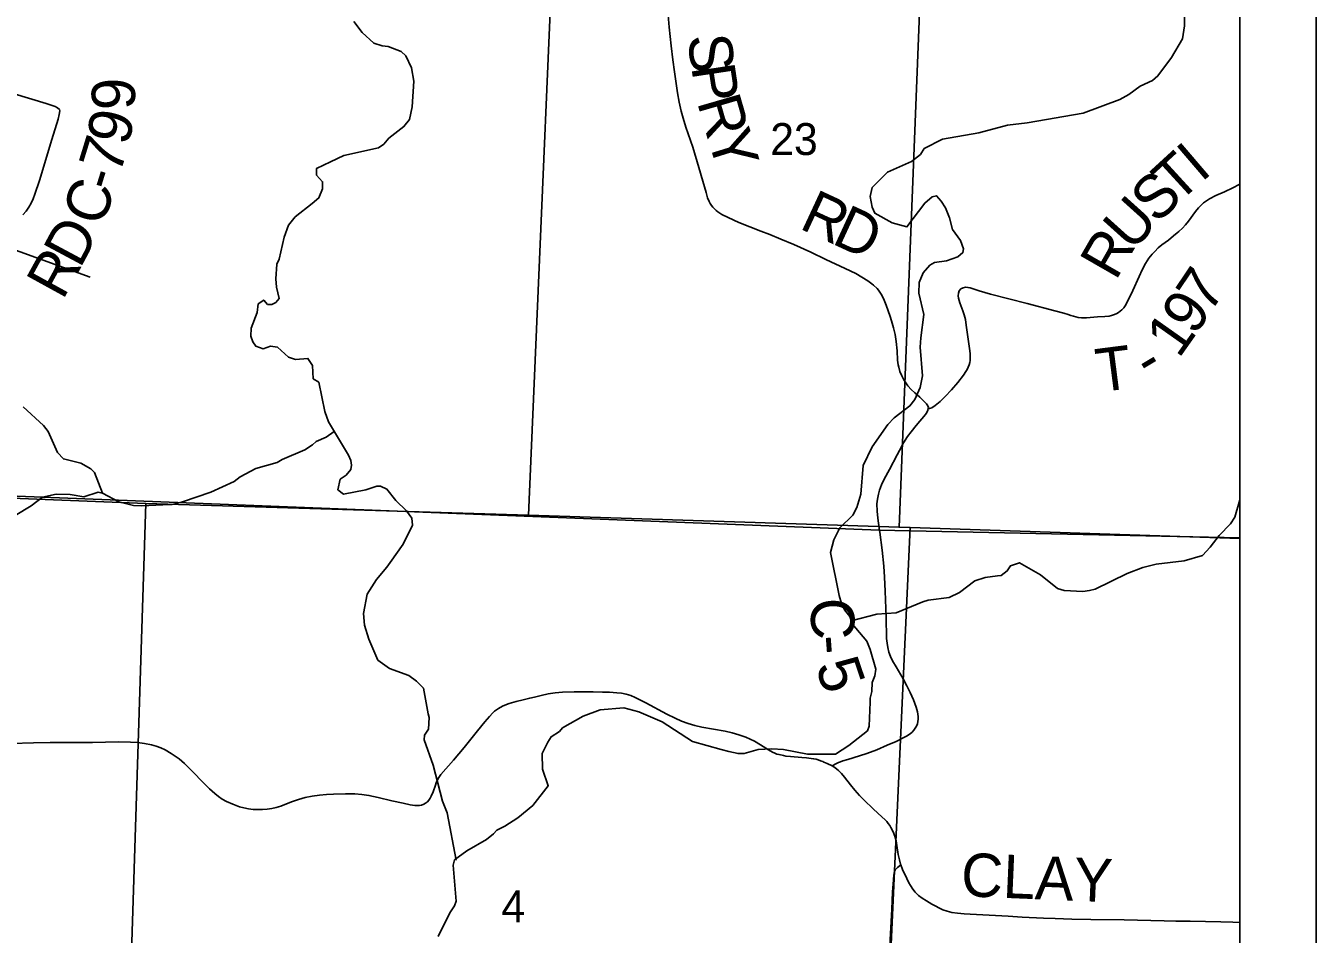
# Model space of a CAD drawing. Extents: x 0 to 34, y 0 to 22.
# Drawn here: x 7.308 to 9, y 14.614 to 15.804 of the extents above; entities that cross this region are included whole.
import ezdxf

# ---------------------------------------------------------------- set-up
doc = ezdxf.new("R2010")
doc.units = 0
for name, color, linetype in [('GM_X_County_Road', 7, 'Continuous'), ('GM_X_County_Road_Text', 7, 'Continuous'), ('GM_X_Minor_River', 7, 'Continuous'), ('GM_X_Rail_Line', 7, 'Continuous'), ('GM_X_Section', 7, 'Continuous'), ('GM_X_Section_Text', 7, 'Continuous'), ('GM_X_Township_Road', 7, 'Continuous'), ('GM_X_Township_Road_Text', 7, 'Continuous'), ('GM_X_Unincorporated_Text', 7, 'Continuous'), ('SH_Data', 7, 'Continuous')]:
    doc.layers.add(name, color=color, linetype=linetype)

msp = doc.modelspace()

# ---------------------------------------------------------------- linework, layer by layer
at = {"layer": 'GM_X_County_Road'}
msp.add_line((7.2752, 15.5169), (7.3927, 15.4747), dxfattribs=at)
for points in [[(8.4914, 15.3023), (8.4917, 15.3036), (8.491, 15.3058), (8.4889, 15.3085), (8.4859, 15.3116), (8.4804, 15.3172), (8.4737, 15.3231), (8.469, 15.3274), (8.4647, 15.3323), (8.461, 15.3372), (8.4594, 15.3398), (8.4566, 15.3451), (8.4543, 15.3508), (8.4527, 15.3567), (8.4521, 15.3596), (8.4512, 15.3656), (8.4504, 15.3778), (8.4495, 15.3901), (8.4481, 15.3993), (8.4459, 15.4083), (8.4433, 15.4172), (8.4413, 15.4231), (8.4362, 15.4378), (8.4327, 15.4465), (8.4298, 15.4521), (8.4263, 15.4573), (8.4242, 15.4597), (8.4197, 15.4641), (8.4173, 15.466), (8.4122, 15.4697), (8.4043, 15.4747), (8.3962, 15.4792), (8.3824, 15.4859), (8.3572, 15.4979), (8.3376, 15.5071), (8.315, 15.5173), (8.2979, 15.5245), (8.2835, 15.5304), (8.2719, 15.5349), (8.2575, 15.5404), (8.2431, 15.5462), (8.229, 15.5526), (8.2208, 15.5568), (8.2156, 15.56), (8.2132, 15.5619), (8.211, 15.5639), (8.2089, 15.5661), (8.2071, 15.5685), (8.2055, 15.571), (8.204, 15.5737), (8.2021, 15.5783), (8.2, 15.5855), (8.1958, 15.6002), (8.1907, 15.6181), (8.1825, 15.6449), (8.1736, 15.6713), (8.1699, 15.683), (8.1675, 15.6919), (8.1649, 15.704), (8.1628, 15.7162), (8.1585, 15.7438), (8.1563, 15.7592), (8.1541, 15.7776), (8.1516, 15.8023), (8.1505, 15.8177)], [(7.2128, 15.7391), (7.2661, 15.7227), (7.293, 15.7146), (7.3349, 15.7022), (7.3438, 15.6992), (7.3467, 15.698), (7.3496, 15.6965), (7.3525, 15.6944)], [(7.3041, 15.5564), (7.3084, 15.561), (7.3121, 15.5661), (7.3153, 15.5716), (7.3179, 15.5774), (7.3201, 15.5832), (7.3259, 15.6011), (7.3422, 15.6548), (7.3504, 15.6817), (7.3519, 15.6878), (7.3526, 15.6925), (7.3525, 15.6944)], [(8.4277, 15.1404), (8.4275, 15.1424), (8.4252, 15.1585), (8.4242, 15.1677), (8.424, 15.1775), (8.4248, 15.1838), (8.426, 15.1901), (8.4275, 15.1954), (8.4299, 15.2022), (8.4334, 15.2097), (8.4405, 15.2224), (8.4507, 15.2417), (8.4536, 15.2472), (8.4591, 15.2573), (8.4642, 15.2659), (8.4689, 15.272), (8.4754, 15.2802), (8.4878, 15.2946), (8.4896, 15.2974), (8.491, 15.3003), (8.4914, 15.3023)], [(8.3655, 14.834), (8.3709, 14.8372), (8.3737, 14.8386), (8.3764, 14.8395), (8.3793, 14.8407), (8.3859, 14.8425), (8.3931, 14.8445), (8.4109, 14.8502), (8.424, 14.8553), (8.4377, 14.8612), (8.4493, 14.8661), (8.4628, 14.8728), (8.4677, 14.8761), (8.4703, 14.8784), (8.4723, 14.8809), (8.4743, 14.8834), (8.4759, 14.8862), (8.4771, 14.8892), (8.4779, 14.8924), (8.4782, 14.8955), (8.4782, 14.8987), (8.4778, 14.9019), (8.4772, 14.905), (8.4756, 14.9111), (8.472, 14.9208), (8.4677, 14.9302), (8.4634, 14.939), (8.4583, 14.9482), (8.4491, 14.9638), (8.4444, 14.9718), (8.4418, 14.9773), (8.4397, 14.9831), (8.4383, 14.989), (8.4373, 14.9951), (8.4367, 15.0012), (8.4362, 15.0291), (8.4349, 15.0632), (8.434, 15.0816), (8.4332, 15.0958), (8.4309, 15.1168), (8.4277, 15.1404)], [(7.2593, 14.8625), (7.3183, 14.8641), (7.34, 14.8645), (7.374, 14.8646), (7.3957, 14.8649), (7.4298, 14.8656), (7.4453, 14.8653), (7.4547, 14.8646), (7.4639, 14.8633), (7.4731, 14.8615), (7.4792, 14.8598), (7.4851, 14.8576), (7.4908, 14.855), (7.4989, 14.8503), (7.5041, 14.8469), (7.5091, 14.8432), (7.5162, 14.837), (7.5273, 14.8261), (7.5402, 14.8127), (7.5491, 14.804), (7.556, 14.7979), (7.5608, 14.794), (7.5658, 14.7906), (7.5711, 14.7876), (7.5795, 14.7838), (7.5882, 14.7806), (7.594, 14.779), (7.6, 14.7778), (7.6061, 14.7771), (7.6122, 14.7767), (7.6183, 14.7768), (7.6244, 14.7772), (7.6305, 14.7781), (7.6364, 14.7795), (7.6423, 14.7814), (7.6566, 14.7871), (7.6655, 14.7902), (7.6746, 14.7926), (7.6838, 14.7943), (7.6931, 14.7955), (7.7024, 14.7964), (7.7117, 14.7968), (7.7272, 14.7973), (7.7395, 14.7973), (7.7488, 14.7967), (7.758, 14.7953), (7.7701, 14.7927), (7.788, 14.7883), (7.8031, 14.785), (7.8121, 14.7831), (7.8182, 14.7822), (7.8212, 14.782), (7.8242, 14.7822), (7.8271, 14.7828), (7.8298, 14.7838), (7.8324, 14.7852), (7.8346, 14.7871), (7.8366, 14.7893), (7.8383, 14.7917), (7.8397, 14.7944), (7.8421, 14.8), (7.8451, 14.8089), (7.8462, 14.8118), (7.849, 14.8175), (7.8525, 14.8227), (7.8687, 14.8416), (7.8829, 14.858), (7.9003, 14.8798), (7.91, 14.8919), (7.9161, 14.899), (7.9203, 14.9036), (7.9226, 14.9057), (7.9251, 14.9076), (7.9277, 14.9094), (7.9332, 14.9125), (7.9361, 14.9138), (7.942, 14.9159), (7.9511, 14.9183), (7.9601, 14.9205), (7.9689, 14.9229), (7.9749, 14.9242), (7.9839, 14.9265), (7.993, 14.9284), (8.0022, 14.9298), (8.0116, 14.9306), (8.0271, 14.9311), (8.052, 14.931), (8.0643, 14.9308), (8.0736, 14.9306), (8.083, 14.93), (8.0892, 14.9292), (8.0953, 14.9279), (8.1014, 14.9262), (8.1072, 14.9238), (8.1211, 14.9168), (8.1484, 14.902), (8.1595, 14.8965), (8.1679, 14.8927), (8.1766, 14.8895), (8.1855, 14.8869), (8.1945, 14.885), (8.2098, 14.8822), (8.2251, 14.8794), (8.2342, 14.8773), (8.2432, 14.8747), (8.252, 14.8715), (8.2578, 14.8691), (8.2634, 14.8663), (8.2714, 14.8615), (8.2819, 14.8549), (8.2873, 14.8519), (8.29, 14.8507), (8.2929, 14.8496), (8.2958, 14.8488), (8.3017, 14.8475), (8.3047, 14.847), (8.3107, 14.8463), (8.3258, 14.8452), (8.3319, 14.8447), (8.338, 14.8439), (8.3411, 14.8434), (8.3442, 14.8427), (8.3472, 14.8419), (8.3502, 14.8409), (8.353, 14.8398), (8.3546, 14.8391), (8.3587, 14.8374), (8.3655, 14.834)], [(8.3655, 14.834), (8.3687, 14.8321), (8.3715, 14.8299), (8.3738, 14.8278), (8.3774, 14.8241), (8.3814, 14.8191), (8.3892, 14.8094), (8.395, 14.8022), (8.4011, 14.7952), (8.4076, 14.7886), (8.4189, 14.7781), (8.4258, 14.7718), (8.4349, 14.7632), (8.437, 14.761), (8.439, 14.7586), (8.4409, 14.756), (8.4425, 14.7533), (8.4452, 14.7476), (8.4475, 14.7418), (8.4492, 14.7358), (8.4502, 14.7296), (8.452, 14.7181), (8.4535, 14.7109), (8.455, 14.7054), (8.4554, 14.7042)], [(8.4554, 14.7042), (8.4577, 14.6981), (8.4631, 14.6865), (8.4658, 14.681), (8.4679, 14.6771), (8.471, 14.6723), (8.4742, 14.6686), (8.4786, 14.6644), (8.4835, 14.6606), (8.4892, 14.6572), (8.4962, 14.6529), (8.5103, 14.6456), (8.5162, 14.6436), (8.5222, 14.6421), (8.5296, 14.6411), (8.5384, 14.6401), (8.5465, 14.6396), (8.596, 14.637), (8.6146, 14.636), (8.6425, 14.6347), (8.6579, 14.634), (8.6797, 14.6334), (8.7045, 14.6327), (8.7483, 14.6321), (8.8006, 14.631), (8.8161, 14.6307), (8.8347, 14.6304), (8.8751, 14.6298), (8.8906, 14.6293), (8.9, 14.6289)]]:
    msp.add_lwpolyline(points, dxfattribs=at)
at = {"layer": 'GM_X_Minor_River'}
for points in [[(7.7382, 15.8095), (7.7492, 15.7951), (7.7645, 15.7812), (7.7755, 15.7775), (7.7831, 15.7768), (7.8002, 15.7704), (7.8063, 15.7648), (7.8139, 15.7489), (7.8171, 15.7314), (7.8147, 15.6976), (7.8114, 15.6813), (7.8039, 15.6718), (7.7843, 15.6568), (7.7775, 15.6488), (7.7707, 15.6442), (7.725, 15.6341), (7.7076, 15.6256)], [(8.8274, 15.8178), (8.8275, 15.8038), (8.8246, 15.7871), (8.8104, 15.7623), (8.7924, 15.7383), (8.7852, 15.7322), (8.769, 15.7249), (8.7543, 15.7138), (8.7426, 15.7073), (8.6946, 15.6895), (8.6212, 15.6769), (8.5951, 15.6737), (8.5577, 15.6636), (8.51, 15.6553), (8.4862, 15.643), (8.481, 15.6354), (8.4693, 15.6262), (8.4379, 15.612), (8.418, 15.5921), (8.4151, 15.5803), (8.4178, 15.5663), (8.4213, 15.5584), (8.4441, 15.5456), (8.4634, 15.5404), (8.4867, 15.5717), (8.4965, 15.5797), (8.5022, 15.5813), (8.5083, 15.5741), (8.514, 15.5654), (8.5194, 15.5525), (8.5233, 15.537), (8.5336, 15.5226), (8.5375, 15.5117), (8.5368, 15.5067), (8.53, 15.501), (8.5152, 15.496), (8.4994, 15.4936), (8.4933, 15.4901), (8.4847, 15.4802), (8.4795, 15.4677), (8.4792, 15.4536), (8.4854, 15.4256), (8.4815, 15.3952), (8.4808, 15.383), (8.4837, 15.3451), (8.4808, 15.3299), (8.4737, 15.3143), (8.4673, 15.3059), (8.4466, 15.2902), (8.4383, 15.2814), (8.4177, 15.2521), (8.4061, 15.2277), (8.403, 15.1901), (8.3978, 15.1726), (8.3925, 15.1627), (8.3756, 15.1459), (8.3674, 15.1303), (8.3633, 15.1136), (8.3747, 15.0575), (8.3774, 15.0469), (8.3816, 15.0386), (8.3885, 15.0299), (8.3916, 15.0204)], [(7.6838, 15.5713), (7.6924, 15.5785), (7.6972, 15.5903), (7.6972, 15.5997), (7.6891, 15.6084), (7.6891, 15.6168), (7.7076, 15.6256)], [(7.6838, 15.5713), (7.6615, 15.5537), (7.6525, 15.5426), (7.6469, 15.527), (7.6403, 15.4981), (7.6373, 15.4916), (7.6359, 15.4723), (7.6367, 15.4613), (7.6402, 15.4468), (7.636, 15.4415), (7.6307, 15.4388), (7.6251, 15.4388), (7.6201, 15.4445), (7.6126, 15.4395), (7.6115, 15.4281), (7.6037, 15.4079), (7.6033, 15.3973), (7.606, 15.3897), (7.6098, 15.384), (7.6193, 15.3806), (7.6291, 15.3841), (7.6382, 15.3826), (7.6527, 15.3698), (7.6617, 15.3668), (7.678, 15.368), (7.6841, 15.3586), (7.685, 15.3415), (7.6925, 15.337)], [(7.6925, 15.337), (7.7, 15.2984), (7.705, 15.2848), (7.7314, 15.2413), (7.7345, 15.2345), (7.7353, 15.228), (7.7342, 15.2227), (7.7282, 15.2151), (7.7203, 15.2097), (7.7174, 15.196), (7.7246, 15.19), (7.7541, 15.1959), (7.7685, 15.2005), (7.7734, 15.2006), (7.7817, 15.1965), (7.7932, 15.1817), (7.8073, 15.1685), (7.8142, 15.1587), (7.815, 15.1496), (7.8027, 15.1245), (7.7858, 15.1008), (7.7813, 15.0947), (7.7678, 15.0783), (7.7558, 15.0593), (7.751, 15.0338), (7.7523, 15.0186), (7.7581, 15.0001), (7.7696, 14.9728), (7.7852, 14.9615), (7.8103, 14.9526), (7.8206, 14.9451), (7.8294, 14.936), (7.8356, 14.9023), (7.8368, 14.8973), (7.8362, 14.8822), (7.8309, 14.8742), (7.8306, 14.8681), (7.8422, 14.8348), (7.8546, 14.7878), (7.8604, 14.7726), (7.8726, 14.7105)], [(7.6839, 15.2549), (7.6741, 15.2484), (7.6443, 15.2357), (7.6379, 15.2315), (7.6099, 15.2237), (7.5892, 15.213), (7.5812, 15.2069), (7.5507, 15.1927), (7.5137, 15.1799), (7.5001, 15.1768), (7.4876, 15.1764), (7.4604, 15.1747), (7.4494, 15.1754), (7.4301, 15.1802), (7.4088, 15.1915), (7.3981, 15.2184), (7.3935, 15.2233), (7.3803, 15.2309), (7.3575, 15.2364), (7.3499, 15.2447), (7.3373, 15.2724), (7.3312, 15.28), (7.3046, 15.3045)], [(7.6839, 15.2549), (7.6889, 15.2593), (7.7021, 15.265), (7.7126, 15.2723)], [(7.41, 15.1909), (7.4028, 15.193), (7.3843, 15.1868), (7.3661, 15.1898), (7.3479, 15.19), (7.3302, 15.1862), (7.3151, 15.1747), (7.294, 15.1624)], [(8.3903, 15.0243), (8.4241, 15.0331), (8.4495, 15.0348), (8.4842, 15.0491), (8.4914, 15.0514), (8.5186, 15.0546), (8.5322, 15.0615), (8.5526, 15.0768), (8.5662, 15.0811), (8.5821, 15.0831), (8.587, 15.0835), (8.5949, 15.0896), (8.599, 15.0961), (8.6108, 15.1003), (8.6385, 15.0846), (8.661, 15.0665), (8.6697, 15.0639), (8.694, 15.0625), (8.7027, 15.0637), (8.7102, 15.0657), (8.7521, 15.0864), (8.7725, 15.0942), (8.7903, 15.0984), (8.827, 15.1028), (8.8508, 15.1098), (8.861, 15.1205), (8.8726, 15.1362), (8.8877, 15.1514), (8.8933, 15.1602), (8.9, 15.1826)], [(8.3916, 15.0204), (8.4107, 14.9977), (8.4153, 14.9868), (8.4227, 14.961), (8.4213, 14.9519), (8.4179, 14.9435), (8.4176, 14.9314), (8.4154, 14.9226), (8.4154, 14.9177), (8.4141, 14.8862), (8.4115, 14.8801), (8.3874, 14.8606), (8.3697, 14.8495), (8.3329, 14.8496), (8.3015, 14.8555), (8.2863, 14.8565), (8.2685, 14.8557), (8.25, 14.8502), (8.242, 14.8502), (8.2299, 14.8528), (8.2197, 14.8557), (8.1821, 14.8661), (8.1425, 14.8917), (8.1121, 14.9048), (8.0924, 14.9103), (8.0614, 14.9075), (8.0391, 14.8994), (8.0119, 14.884), (8.0078, 14.8791), (7.9968, 14.8722), (7.9927, 14.8653), (7.9852, 14.8501), (7.9854, 14.8296), (7.9931, 14.808), (7.9728, 14.7821), (7.9532, 14.766), (7.9363, 14.7549), (7.9257, 14.7499), (7.9212, 14.7449), (7.9121, 14.7377), (7.8865, 14.7227), (7.8703, 14.7108), (7.8684, 14.704), (7.8722, 14.6566), (7.8703, 14.6505), (7.8639, 14.6417), (7.849, 14.6105)]]:
    msp.add_lwpolyline(points, dxfattribs=at)
at = {"layer": 'GM_X_Rail_Line'}
msp.add_lwpolyline([(6.4764, 15.22), (8.4272, 15.1429), (8.9, 15.1329), (8.9, 20.2439), (7.9141, 20.2806), (7.3096, 20.3035), (6.6357, 20.3306)], dxfattribs=at)
msp.add_lwpolyline([(6.4223, 14.1), (8.9, 14.1), (8.9, 15.1329), (8.4272, 15.1429), (6.4764, 15.22), (6.4607, 14.8895)], close=True, dxfattribs=at)
at = {"layer": 'GM_X_Section'}
for points in [[(8.0113, 16.1881), (8.4938, 16.1751), (8.4531, 15.1468), (7.9673, 15.1628)], [(7.4655, 15.1779), (7.4338, 14.1789), (6.4272, 14.2142), (6.4755, 15.2172)], [(7.4655, 15.1779), (7.9673, 15.1628), (8.4531, 15.1468), (8.4675, 15.1465), (8.4218, 14.1405), (7.4338, 14.1789)]]:
    msp.add_lwpolyline(points, close=True, dxfattribs=at)
at = {"layer": 'GM_X_Township_Road'}
for points in [[(8.4914, 15.3023), (8.4931, 15.3023), (8.496, 15.3035), (8.5006, 15.3062), (8.5069, 15.3116), (8.5135, 15.318), (8.5217, 15.3269), (8.5301, 15.3365), (8.5376, 15.3459), (8.5408, 15.3508), (8.5426, 15.3537), (8.5439, 15.3565), (8.545, 15.3597), (8.5458, 15.3625), (8.5463, 15.3654), (8.5464, 15.3686), (8.5463, 15.3747), (8.5456, 15.381), (8.5438, 15.3933), (8.5426, 15.4024), (8.5411, 15.4118), (8.54, 15.4189), (8.5384, 15.4253), (8.5367, 15.4305), (8.5327, 15.4411), (8.5318, 15.4441), (8.5311, 15.4472), (8.5308, 15.4503), (8.5311, 15.4535), (8.5321, 15.4566), (8.5341, 15.4591), (8.537, 15.4607), (8.5401, 15.4614), (8.5434, 15.4612), (8.5464, 15.4605), (8.5582, 15.4566), (8.5731, 15.4522), (8.6212, 15.4401), (8.6573, 15.4306), (8.6692, 15.4274), (8.675, 15.4255), (8.6785, 15.4243), (8.6817, 15.4235), (8.6848, 15.4225), (8.6881, 15.4219), (8.6924, 15.4213), (8.6988, 15.4213), (8.7131, 15.4225), (8.723, 15.423), (8.7286, 15.4236), (8.7317, 15.4242), (8.7356, 15.4256), (8.7385, 15.4269), (8.7406, 15.4283), (8.7429, 15.4298), (8.7453, 15.4316), (8.7478, 15.4343), (8.7495, 15.4368), (8.7528, 15.4426), (8.7594, 15.4571), (8.7678, 15.4755), (8.7718, 15.4841), (8.7761, 15.4924), (8.7807, 15.4994), (8.785, 15.5048), (8.7883, 15.5081), (8.7929, 15.5131), (8.7976, 15.5168), (8.8063, 15.5232), (8.8128, 15.5287), (8.8176, 15.5325), (8.82, 15.5344), (8.8245, 15.5386), (8.8286, 15.5431), (8.8324, 15.5479), (8.8416, 15.5604), (8.8456, 15.5652), (8.8499, 15.5697), (8.8522, 15.5718), (8.8547, 15.5738), (8.86, 15.5771), (8.8683, 15.5814), (8.8796, 15.5865), (8.8909, 15.5916), (8.8992, 15.5958), (8.9, 15.5963)], [(8.4407, 14.5901), (8.4434, 14.6462), (8.4447, 14.6688), (8.4453, 14.6792), (8.4464, 14.6908), (8.4471, 14.6957), (8.4481, 14.6978), (8.4496, 14.6998), (8.4509, 14.7009), (8.4526, 14.7021), (8.4554, 14.7042)]]:
    msp.add_lwpolyline(points, dxfattribs=at)
at = {"layer": 'GM_X_Unincorporated_Text'}
for points in [[(8.9, 15.1321), (8.9, 16.1585), (8.4938, 16.1751), (8.4531, 15.1468), (8.4675, 15.1465)], [(8.9, 14.1266), (8.9, 15.1321), (8.4675, 15.1465), (8.4218, 14.1405)]]:
    msp.add_lwpolyline(points, close=True, dxfattribs=at)
at = {"layer": 'SH_Data'}
for p, q in [((9, 21), (9, 14)), ((8.9, 20.9), (8.9, 14.1))]:
    msp.add_line(p, q, dxfattribs=at)

# ---------------------------------------------------------------- texts
at = {"layer": 'GM_X_County_Road_Text'}
for s, height, rotation, p in [('S', 0.0568, 276.6813, (8.1757, 15.7904)), ('P', 0.0568, 278.5845, (8.1805, 15.7503)), ('9', 0.0568, 90.5671, (7.4516, 15.6938)), ('R', 0.0568, 286.155, (8.1879, 15.7044)), ('9', 0.0568, 77.4973, (7.4425, 15.6456)), ('Y', 0.0568, 287.3444, (8.2013, 15.6583)), ('7', 0.0568, 72.8829, (7.431, 15.6073)), ('C', 0.0568, 71.4305, (7.4087, 15.5393)), ('-', 0.0568, 72.7545, (7.424, 15.5849)), ('R', 0.0568, 335.0515, (8.3207, 15.5391)), ('D', 0.0568, 335.211, (8.3632, 15.5193)), ('D', 0.0568, 61.8656, (7.3792, 15.4848)), ('R', 0.0568, 61.2229, (7.3565, 15.4433)), ('C', 0.0568, 271.0734, (8.3371, 15.0538)), ('-', 0.0568, 274.2242, (8.3382, 15.0037)), ('5', 0.0568, 288.5471, (8.343, 14.9653)), ('CLAY', 0.05682, 357.6028, (8.5335, 14.6635))]:
    msp.add_text(s, height=height, rotation=rotation, dxfattribs=at).set_placement(p)
at = {"layer": 'GM_X_Section_Text'}
for s, height, p in [('23', 0.04186, (8.2842, 15.6346)), ('4', 0.0419, (7.9317, 14.629))]:
    msp.add_text(s, height=height, rotation=0, dxfattribs=at).set_placement(p)
at = {"layer": 'GM_X_Township_Road_Text'}
for s, rotation, p in [('I', 40.5412, (8.8492, 15.598)), ('T', 42.4962, (8.8182, 15.5696)), ('S', 44.5733, (8.7913, 15.5431)), ('U', 47.9971, (8.7585, 15.5066)), ('R', 60.1307, (8.7371, 15.4687)), ('7', 55.9736, (8.8603, 15.4257)), ('9', 56.2007, (8.8409, 15.3966)), ('1', 54.7933, (8.8198, 15.3668)), ('T', 7.3398, (8.7149, 15.3236)), ('-', 30.8583, (8.7809, 15.3373))]:
    msp.add_text(s, height=0.0568, rotation=rotation, dxfattribs=at).set_placement(p)

doc.saveas('drawing.dxf')
